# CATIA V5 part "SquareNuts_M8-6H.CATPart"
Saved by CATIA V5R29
Part number: SquareNuts_M8-6H
Source: Unknown
Bounding box of the stored display mesh (mm): x -7 to 7, y -7 to 7, z -3 to 3
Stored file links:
  C:\가치같이\SmartFactory_BoxErectorConveyor\Boxing(under)\SquareNuts_M8-6H.CATPart
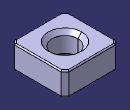
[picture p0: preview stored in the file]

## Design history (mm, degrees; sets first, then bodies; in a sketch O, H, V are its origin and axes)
Body1 (main body)
  Solid1 "PartBody": solid without history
